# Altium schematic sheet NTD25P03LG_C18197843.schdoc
size 127 x 101 mm
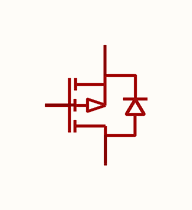
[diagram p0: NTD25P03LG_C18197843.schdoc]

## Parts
Q?  ntd25p03lg  [TO-252-3_L6.6-W6.1-P4.57-LS9.9-BR-CW]  (value not drawn)

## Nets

Not connected (* = marked no-connect by the designer): Q? 1(G) 2(D) 3(S)

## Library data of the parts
Q? = ntd25p03lg: 漏源电压(Vdss):30V;连续漏极电流(Id):30A;导通电阻(RDS(on)):32mΩ@10V,5.3A;耗散功率(Pd):50W;阈值电压(Vgs(th)):3V@250uA;; Manufacturer: TECH PUBLIC(台舟); Symbol: NTD25P03LG_C18197843; AddInBom: yes; ModelId: dee852f3c6b348a2b9d5be5dd3244081; ModelTransform: 258.97184,390.1567,0,90,0,0,-35.433,0,0; Drain to Source Voltage: 30V; Current - Continuous Drain(Id): 30A; Pd - Power Dissipation: 50W; Gate Charge(Qg): 31nC@10V; Input Capacitance(Ciss): 1.13nF; Reverse Transfer Capacitance (Crss@Vds): 180pF; Type: P沟道; Output Capacitance(Coss): 220pF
